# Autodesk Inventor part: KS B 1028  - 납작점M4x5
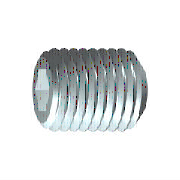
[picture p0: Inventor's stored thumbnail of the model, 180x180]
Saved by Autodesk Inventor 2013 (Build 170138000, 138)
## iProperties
IsCustomPart: 0
Created: 2009-02
Part Number: KS B 1028  - 납작점M4x5
Material: Steel, Mild
Description: 6각 소켓 머리 없는 멈춤 나사
Document SubType Name: Modeling
Standard: KS B 1028
Designer: KYOUNG IL JANG
Standards Organization: KS
Language: ko-KR
Size Designation: 납작점M4x5
Categories: <MemberInstance><Categories><Category DisplayName="조임쇠" InternalName="e4da775c-781d-43d5-af7c-5136215cf5a6" Mnemonic="FSTN"><Category DisplayName="볼트" InternalN
Density: 7.86 g/cm^3
Mass: 0.401763 g
Surface Area: 0.994256 cm^2
Volume: 0.0511149 cm^3
Author: KYOUNG IL JANG
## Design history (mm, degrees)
sketch "스케치1"
  geometry: L1 (0, 0)-(1.833, 0); L2 (5, 1.155)-(5, 2); L3 (5, 2)-(0, 2); L4 (5, 1.155)-(2.5, 1.155); L5 (2.5, 1.155)-(1.833, 0); L6 (0, -0.4)-(0, 2.4) reference; L7 (0, 2)-(0, 0)
  constraints: 13 end point, 3 parallel, 1 collinear, 1 perpendicular, 1 point on line
  dimensions: "d0" = 2.5 distance of L2.start L4.end (= INTI); "d1" = 60 deg angle of L5 L1; "d2" = 4 diameter of L3 L1 (= NND); "d3" = 2.3094 diameter of L4 L1 (= 1.1547 x SW); "d5" = 5 distance from line of L2 L3.end (= NLG)
revolve "본체" sketch "스케치1" stored, may be unused: angle "d6" = 90 deg
sketch "스케치2"
  geometry: L1 (-0.577, 1)-(0.577, 1); L2 (0.577, 1)-(1.155, 0); L3 (1.155, 0)-(0.577, -1); L4 (0.577, -1)-(-0.577, -1); L5 (-0.577, -1)-(-1.155, 0); L6 (-1.155, 0)-(-0.577, 1); A1 r 1.155 centre (0, 0) between (-0.577, 1) and (0.577, 1) reference; 2 further points
  constraints: 12 end point, 2 point on circle, 1 coincident, 1 horizontal, 11 other
extrude "슬롯" join sketch "스케치2" taper "d9" = 0 deg; stored distance "d21" = 10
workaxis "Work Axis1"
workplane "Work Plane1"
body "Solid1"
chamfer "모따기1" distance "d7" = 0.42941 (= -0.5 x GD1 + 0.5 x NND); stored, may be unused: angle "d8" = 45 deg (= FAWI), second distance "d29" = 0.42941 (= -0.5 x GD1 + 0.5 x NND)
feature "스레드" dims "d11" = 5 (= NLG), "d12" = 0
chamfer "모따기2" distance "d13" = 0.42941 (= -0.5 x GD1 + 0.5 x NND); stored, may be unused: angle "d14" = 45 deg (= FAWI), second distance "d30" = 0.42941 (= -0.5 x GD1 + 0.5 x NND)
other parameters: "NND" = 4 [user parameter; used in 5 equation terms], "NLG" = 5 [user parameter; used in 2 equation terms], "INTI" = 2.5 [user parameter; used in 1 equation term], "FAWI" = 45 deg [user parameter; used in 2 equation terms], "SW" = 2 [user parameter; used in 2 equation terms], "GD1" = 3.14117 (= THREADDIA - 1.2269 x PTC) [user parameter; used in 4 equation terms], "d4" = 0, "FAWI1" = 45 deg [user parameter], "d15" = 0, "d31" = 0, "GUL" = 0.42941 (= 0.61345 x PTC) [user parameter], "SPD" = 2.5 [user parameter], "TPU" = 14.28571 (computed from PTC) [user parameter], "TOA" = 30 deg [user parameter], "THREADDIA" = 4 [user parameter; used in 1 equation term], "PTC" = 0.7 [user parameter; used in 4 equation terms], "GAL" = 0.42941 (= 0.61345 x PTC) [user parameter], "E0" = 2.31 (= 1.155 x SW) [user parameter]
